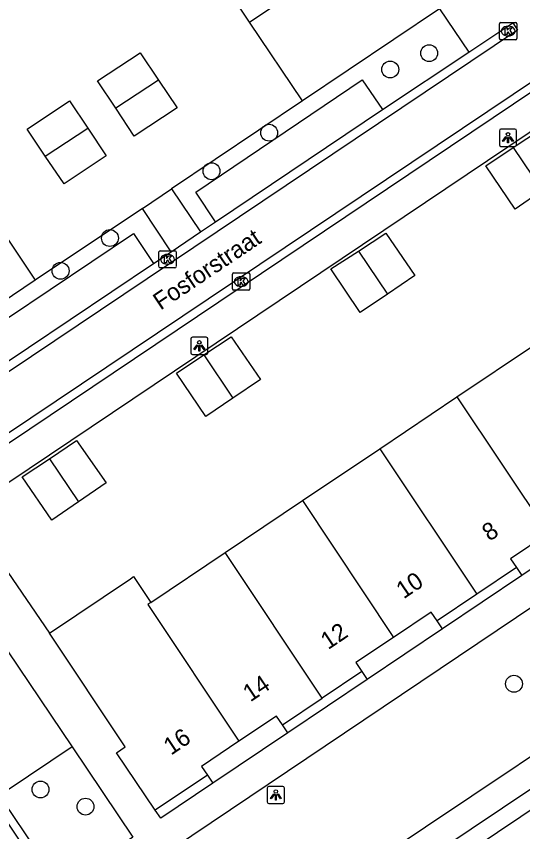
# Model space of a CAD drawing. Extents: x 158797 to 159887, y 384318 to 385255.
# Drawn here: x 159163.97 to 159193.34, y 384481.97 to 384529.23 of the extents above; entities that cross this region are included whole.
import ezdxf

# ---------------------------------------------------------------- set-up
doc = ezdxf.new("R2010")
doc.units = 0
for name, color, linetype in [('IMGEO_Boom', 7, 'Continuous'), ('IMGEO_Groenvoorziening', 7, 'Continuous'), ('IMGEO_Kolk', 7, 'Continuous'), ('IMGEO_Lichtpunt', 7, 'Continuous'), ('IMGEO_Openbare_ruimte_label', 7, 'Continuous'), ('IMGEO_Pand', 7, 'Continuous'), ('IMGEO_Pand_nummerreeks', 7, 'Continuous'), ('IMGEO_Parkeervlak_open', 7, 'Continuous'), ('IMGEO_Rijbaan_lokaal_open', 7, 'Continuous'), ('IMGEO_Voetpad_gesloten', 7, 'Continuous'), ('IMGEO_Voetpad_open', 7, 'Continuous')]:
    doc.layers.add(name, color=color, linetype=linetype)

msp = doc.modelspace()

# ---------------------------------------------------------------- linework, layer by layer
at = {"layer": 'IMGEO_Boom'}
for centre in [(159187.914, 384527.094), (159185.658, 384526.151), (159178.634, 384522.484), (159175.292, 384520.251), (159169.403, 384516.38), (159166.541, 384514.479), (159192.832, 384490.548), (159165.374, 384484.417), (159167.987, 384483.425)]:
    msp.add_circle(centre, 0.489, dxfattribs=at)
at = {"layer": 'IMGEO_Groenvoorziening'}
for points in [[(159180.569, 384524.332), (159172.974, 384519.236)], [(159171.283, 384518.101), (159165.067, 384513.931)], [(159173.77, 384469.796), (159218.275, 384499.657), (159225.084, 384489.227), (159180.738, 384459.571), (159173.77, 384469.796)], [(159192.976, 384497.285), (159193.291, 384496.817)], [(159188.691, 384493.728), (159188.376, 384494.197)], [(159184.009, 384491.264), (159184.323, 384490.796)], [(159179.716, 384487.702), (159179.402, 384488.17)], [(159175.052, 384485.249), (159175.368, 384484.782)]]:
    msp.add_lwpolyline(points, dxfattribs=at)
at = {"layer": 'IMGEO_Kolk'}
for p, q in [((159191.993, 384527.947), (159191.993, 384528.799)), ((159192.068, 384528.873), (159192.92, 384528.873)), ((159192.481, 384528.653), (159192.506, 384528.653)), ((159192.994, 384528.799), (159192.994, 384527.947)), ((159192.504, 384528.093), (159192.479, 384528.093)), ((159192.92, 384527.873), (159192.068, 384527.873)), ((159172.246, 384514.721), (159172.246, 384515.573)), ((159172.321, 384515.647), (159173.173, 384515.647)), ((159172.734, 384515.427), (159172.759, 384515.427)), ((159173.247, 384515.573), (159173.247, 384514.721)), ((159172.757, 384514.867), (159172.732, 384514.867)), ((159173.173, 384514.647), (159172.321, 384514.647)), ((159176.585, 384514.358), (159177.437, 384514.358)), ((159176.51, 384513.432), (159176.51, 384514.284)), ((159176.998, 384514.138), (159177.023, 384514.138)), ((159177.511, 384514.284), (159177.511, 384513.432)), ((159177.021, 384513.578), (159176.996, 384513.578)), ((159177.437, 384513.358), (159176.585, 384513.358))]:
    msp.add_line(p, q, dxfattribs=at)
for points in [[(159191.993, 384527.947), (159191.993, 384528.799)], [(159192.068, 384528.873), (159192.92, 384528.873)], [(159192.314, 384528.573), (159192.437, 384528.573), (159192.437, 384528.422), (159192.567, 384528.573), (159192.731, 384528.573), (159192.585, 384528.422), (159192.738, 384528.173), (159192.586, 384528.173), (159192.501, 384528.337), (159192.437, 384528.27), (159192.437, 384528.173), (159192.314, 384528.173), (159192.314, 384528.573)], [(159192.994, 384528.799), (159192.994, 384527.947)], [(159192.92, 384527.873), (159192.068, 384527.873)], [(159172.246, 384514.721), (159172.246, 384515.573)], [(159172.321, 384515.647), (159173.173, 384515.647)], [(159172.567, 384515.347), (159172.69, 384515.347), (159172.69, 384515.196), (159172.82, 384515.347), (159172.984, 384515.347), (159172.838, 384515.196), (159172.991, 384514.947), (159172.839, 384514.947), (159172.754, 384515.111), (159172.69, 384515.044), (159172.69, 384514.947), (159172.567, 384514.947), (159172.567, 384515.347)], [(159173.247, 384515.573), (159173.247, 384514.721)], [(159173.173, 384514.647), (159172.321, 384514.647)], [(159176.585, 384514.358), (159177.437, 384514.358)], [(159176.51, 384513.432), (159176.51, 384514.284)], [(159176.831, 384514.058), (159176.954, 384514.058), (159176.954, 384513.907), (159177.084, 384514.058), (159177.248, 384514.058), (159177.102, 384513.907), (159177.255, 384513.658), (159177.103, 384513.658), (159177.018, 384513.822), (159176.954, 384513.755), (159176.954, 384513.658), (159176.831, 384513.658), (159176.831, 384514.058)], [(159177.511, 384514.284), (159177.511, 384513.432)], [(159177.437, 384513.358), (159176.585, 384513.358)]]:
    msp.add_lwpolyline(points, dxfattribs=at)
for centre, start, end in [((159192.07, 384528.797), 91.552, 178.448), ((159192.07, 384528.797), 91.552, 178.448), ((159192.918, 384528.797), 1.552, 88.448), ((159192.918, 384528.797), 1.552, 88.448), ((159192.07, 384527.949), 181.552, 268.448), ((159192.07, 384527.949), 181.552, 268.448), ((159192.918, 384527.949), 271.552, 358.448), ((159192.918, 384527.949), 271.552, 358.448), ((159172.323, 384515.571), 91.552, 178.448), ((159172.323, 384515.571), 91.552, 178.448), ((159173.171, 384515.571), 1.552, 88.448), ((159173.171, 384515.571), 1.552, 88.448), ((159172.323, 384514.723), 181.552, 268.448), ((159172.323, 384514.723), 181.552, 268.448), ((159173.171, 384514.723), 271.552, 358.448), ((159173.171, 384514.723), 271.552, 358.448), ((159176.587, 384514.282), 91.552, 178.448), ((159176.587, 384514.282), 91.552, 178.448), ((159177.435, 384514.282), 1.552, 88.448), ((159177.435, 384514.282), 1.552, 88.448), ((159176.587, 384513.434), 181.552, 268.448), ((159176.587, 384513.434), 181.552, 268.448), ((159177.435, 384513.434), 271.552, 358.448), ((159177.435, 384513.434), 271.552, 358.448)]:
    msp.add_arc(centre, 0.0765, start, end, dxfattribs=at)
for centre, major_axis, ratio, start_param, end_param in [((159192.48, 384528.373), (-0.387, 0.002), 0.722429, 4.712389, 7.853982), ((159192.505, 384528.373), (-0.39, 0.002), 0.717154, 1.570796, 4.712389), ((159172.733, 384515.147), (-0.387, 0.002), 0.722429, 4.712389, 7.853982), ((159172.758, 384515.147), (-0.39, 0.002), 0.717154, 1.570796, 4.712389), ((159176.997, 384513.858), (-0.387, 0.002), 0.722429, 4.712389, 7.853982), ((159177.022, 384513.858), (-0.39, 0.002), 0.717154, 1.570796, 4.712389)]:
    msp.add_ellipse(centre, major_axis=major_axis, ratio=ratio, start_param=start_param, end_param=end_param, dxfattribs=at)
at = {"layer": 'IMGEO_Lichtpunt'}
for p, q in [((159191.984, 384522.595), (159191.984, 384521.788)), ((159191.984, 384522.595), (159191.984, 384521.788)), ((159192.886, 384522.69), (159192.078, 384522.69)), ((159192.886, 384522.69), (159192.078, 384522.69)), ((159192.98, 384521.788), (159192.98, 384522.595)), ((159192.98, 384521.788), (159192.98, 384522.595)), ((159192.078, 384521.694), (159192.886, 384521.694)), ((159192.078, 384521.694), (159192.886, 384521.694)), ((159174.992, 384510.63), (159174.184, 384510.63)), ((159174.992, 384510.63), (159174.184, 384510.63)), ((159174.09, 384510.535), (159174.09, 384509.728)), ((159174.09, 384510.535), (159174.09, 384509.728)), ((159175.086, 384509.728), (159175.086, 384510.535)), ((159175.086, 384509.728), (159175.086, 384510.535)), ((159174.184, 384509.634), (159174.992, 384509.634)), ((159174.184, 384509.634), (159174.992, 384509.634)), ((159179.428, 384484.598), (159178.62, 384484.598)), ((159179.428, 384484.598), (159178.62, 384484.598)), ((159178.526, 384484.503), (159178.526, 384483.696)), ((159178.526, 384484.503), (159178.526, 384483.696)), ((159179.522, 384483.696), (159179.522, 384484.503)), ((159179.522, 384483.696), (159179.522, 384484.503)), ((159178.62, 384483.602), (159179.428, 384483.602)), ((159178.62, 384483.602), (159179.428, 384483.602))]:
    msp.add_line(p, q, dxfattribs=at)
for points in [[(159192.358, 384522.259), (159192.397, 384522.231), (159192.209, 384521.969), (159192.171, 384521.996), (159192.358, 384522.259)], [(159192.46, 384522.211), (159192.507, 384522.211), (159192.507, 384521.889), (159192.46, 384521.889), (159192.46, 384522.211)], [(159192.57, 384522.231), (159192.608, 384522.258), (159192.795, 384521.996), (159192.756, 384521.968), (159192.57, 384522.231)], [(159174.464, 384510.199), (159174.503, 384510.171), (159174.315, 384509.909), (159174.277, 384509.936), (159174.464, 384510.199)], [(159174.566, 384510.151), (159174.613, 384510.151), (159174.613, 384509.829), (159174.566, 384509.829), (159174.566, 384510.151)], [(159174.676, 384510.171), (159174.714, 384510.198), (159174.901, 384509.936), (159174.862, 384509.908), (159174.676, 384510.171)], [(159178.9, 384484.167), (159178.939, 384484.139), (159178.751, 384483.877), (159178.713, 384483.904), (159178.9, 384484.167)], [(159179.002, 384484.119), (159179.049, 384484.119), (159179.049, 384483.797), (159179.002, 384483.797), (159179.002, 384484.119)], [(159179.112, 384484.139), (159179.15, 384484.166), (159179.337, 384483.904), (159179.298, 384483.876), (159179.112, 384484.139)]]:
    msp.add_lwpolyline(points, dxfattribs=at)
for centre in [(159192.483, 384522.393), (159174.589, 384510.333), (159179.025, 384484.301)]:
    msp.add_circle(centre, 0.0994, dxfattribs=at)
for centre, start, end in [((159192.078, 384522.595), 90, 180), ((159192.078, 384522.595), 90, 180), ((159192.886, 384522.595), 0, 90), ((159192.886, 384522.595), 0, 90), ((159192.078, 384521.788), 180, 270), ((159192.078, 384521.788), 180, 270), ((159192.886, 384521.788), 270, 0), ((159192.886, 384521.788), 270, 360), ((159174.184, 384510.535), 90, 180), ((159174.184, 384510.535), 90, 180), ((159174.992, 384510.535), 0, 90), ((159174.992, 384510.535), 0, 90), ((159174.184, 384509.728), 180, 270), ((159174.184, 384509.728), 180, 270), ((159174.992, 384509.728), 270, 0), ((159174.992, 384509.728), 270, 360), ((159178.62, 384484.503), 90, 180), ((159178.62, 384484.503), 90, 180), ((159179.428, 384484.503), 0, 90), ((159179.428, 384484.503), 0, 90), ((159178.62, 384483.696), 180, 270), ((159178.62, 384483.696), 180, 270), ((159179.428, 384483.696), 270, 0), ((159179.428, 384483.696), 270, 360)]:
    msp.add_arc(centre, 0.0946, start, end, dxfattribs=at)
at = {"layer": 'IMGEO_Pand'}
for points in [[(159177.505, 384528.901), (159185.434, 384534.241)], [(159177.505, 384528.901), (159174.43, 384533.484)], [(159188.508, 384529.657), (159180.569, 384524.332)], [(159180.569, 384524.332), (159177.505, 384528.901)], [(159169.749, 384523.899), (159168.689, 384525.5), (159171.15, 384527.115), (159172.224, 384525.525)], [(159172.224, 384525.525), (159173.298, 384523.935), (159170.816, 384522.288), (159169.749, 384523.899)], [(159172.224, 384525.525), (159169.749, 384523.899)], [(159165.654, 384521.126), (159164.596, 384522.688), (159167.049, 384524.341), (159168.121, 384522.748)], [(159168.121, 384522.748), (159169.193, 384521.154), (159166.742, 384519.518), (159165.654, 384521.126)], [(159165.654, 384521.126), (159168.121, 384522.748)], [(159192.785, 384521.624), (159194.37, 384522.675), (159196.055, 384520.211), (159194.469, 384519.13)], [(159194.469, 384519.13), (159192.898, 384518.058), (159191.199, 384520.573), (159192.785, 384521.624)], [(159192.785, 384521.624), (159194.469, 384519.13)], [(159161.993, 384518.519), (159165.067, 384513.931)], [(159183.808, 384515.627), (159185.399, 384516.658), (159187.089, 384514.204), (159185.493, 384513.133)], [(159185.493, 384513.133), (159183.915, 384512.073), (159182.217, 384514.596), (159183.808, 384515.627)], [(159183.808, 384515.627), (159185.493, 384513.133)], [(159165.067, 384513.931), (159155.669, 384507.602)], [(159174.847, 384509.603), (159176.437, 384510.65), (159178.133, 384508.182), (159176.538, 384507.1)], [(159189.525, 384507.179), (159194.017, 384510.196)], [(159176.538, 384507.1), (159174.968, 384506.034), (159173.257, 384508.556), (159174.847, 384509.603)], [(159174.847, 384509.603), (159176.538, 384507.1)], [(159185.047, 384504.172), (159189.525, 384507.179)], [(159189.525, 384507.179), (159194.815, 384499.255)], [(159165.89, 384503.591), (159167.469, 384504.637), (159169.187, 384502.193), (159167.577, 384501.093)], [(159180.563, 384501.16), (159185.047, 384504.172)], [(159185.047, 384504.172), (159190.676, 384495.741)], [(159167.577, 384501.093), (159166.026, 384500.033), (159164.311, 384502.544), (159165.89, 384503.591)], [(159165.89, 384503.591), (159167.577, 384501.093)], [(159176.078, 384498.148), (159180.563, 384501.16)], [(159180.563, 384501.16), (159185.853, 384493.237)], [(159194.815, 384499.255), (159192.635, 384497.791), (159192.976, 384497.285)], [(159171.782, 384495.263), (159176.078, 384498.148)], [(159181.706, 384489.717), (159176.078, 384498.148)], [(159192.976, 384497.285), (159190.676, 384495.741)], [(159165.893, 384493.473), (159170.598, 384496.636), (159170.778, 384496.757), (159171.782, 384495.263)], [(159190.676, 384495.741), (159188.376, 384494.197)], [(159171.782, 384495.263), (159171.597, 384495.139), (159176.887, 384487.216)], [(159188.376, 384494.197), (159188.036, 384494.703), (159185.853, 384493.237)], [(159172.03, 384483.22), (159169.79, 384486.546), (159170.291, 384486.885), (159165.893, 384493.473)], [(159185.853, 384493.237), (159183.669, 384491.771), (159184.009, 384491.264)], [(159184.009, 384491.264), (159181.706, 384489.717)], [(159179.402, 384488.17), (159181.706, 384489.717)], [(159179.402, 384488.17), (159179.062, 384488.677), (159176.887, 384487.216)], [(159176.887, 384487.216), (159174.712, 384485.755), (159175.052, 384485.249)], [(159175.052, 384485.249), (159172.03, 384483.22)]]:
    msp.add_lwpolyline(points, dxfattribs=at)
at = {"layer": 'IMGEO_Parkeervlak_open'}
for points in [[(159175.52, 384517.315), (159174.379, 384519.047), (159184.026, 384525.553), (159185.204, 384523.823)], [(159162.243, 384508.41), (159161.078, 384510.145), (159170.771, 384516.645), (159171.938, 384514.9)], [(159167.208, 384486.885), (159163.448, 384484.359)]]:
    msp.add_lwpolyline(points, dxfattribs=at)
at = {"layer": 'IMGEO_Rijbaan_lokaal_open'}
for points in [[(159190.205, 384527.153), (159192.762, 384528.848), (159193.039, 384528.419), (159151.428, 384500.515), (159133.468, 384527.238), (159175.064, 384555.242), (159175.35, 384554.823), (159172.804, 384553.09)], [(159188.508, 384529.657), (159190.205, 384527.153)], [(159166.119, 384478.572), (159153.048, 384498.068), (159198.654, 384528.669)], [(159198.935, 384528.248), (159153.727, 384497.909), (159155.025, 384496.003)], [(159185.204, 384523.823), (159190.205, 384527.153)], [(159175.52, 384517.315), (159185.204, 384523.823)], [(159174.662, 384516.736), (159175.52, 384517.315)], [(159172.956, 384515.586), (159174.662, 384516.736)], [(159171.938, 384514.9), (159172.956, 384515.586)], [(159162.243, 384508.41), (159171.938, 384514.9)], [(159166.298, 384479.197), (159166.262, 384479.244), (159163.274, 384483.682)]]:
    msp.add_lwpolyline(points, dxfattribs=at)
at = {"layer": 'IMGEO_Voetpad_gesloten'}
for points in [[(159214.687, 384500.279), (159171.524, 384471.418)], [(159172.348, 384470.087), (159215.549, 384499.032)]]:
    msp.add_lwpolyline(points, dxfattribs=at)
at = {"layer": 'IMGEO_Voetpad_open'}
for points in [[(159197.375, 384524.94), (159161.04, 384500.556)], [(159171.283, 384518.101), (159172.974, 384519.236)], [(159172.974, 384519.236), (159174.662, 384516.736)], [(159172.956, 384515.586), (159171.283, 384518.101)], [(159164.23, 384475.096), (159210.619, 384506.269)], [(159161.04, 384500.556), (159165.893, 384493.473)], [(159197.649, 384499.743), (159193.291, 384496.817)], [(159159.736, 384497.97), (159167.208, 384486.885)], [(159193.291, 384496.817), (159188.691, 384493.728)], [(159188.691, 384493.728), (159184.323, 384490.796)], [(159184.323, 384490.796), (159179.716, 384487.702)], [(159179.716, 384487.702), (159175.368, 384484.782)], [(159167.208, 384486.885), (159170.738, 384481.648), (159166.971, 384479.12)], [(159175.368, 384484.782), (159172.349, 384482.755), (159172.03, 384483.22)]]:
    msp.add_lwpolyline(points, dxfattribs=at)

# ---------------------------------------------------------------- texts
at = {"layer": 'IMGEO_Openbare_ruimte_label'}
msp.add_text('Fosforstraat', height=1, rotation=33.8649, dxfattribs=at).set_placement((159172.338, 384512.171))
at = {"layer": 'IMGEO_Pand_nummerreeks'}
for s, rotation, p in [('8', 33.8819, (159191.41, 384498.775)), ('10', 33.8819, (159186.433, 384495.434)), ('12', 33.8819, (159182.053, 384492.492)), ('14', 33.8847, (159177.545, 384489.464)), ('16', 33.8847, (159172.945, 384486.375))]:
    msp.add_text(s, height=1, rotation=rotation, dxfattribs=at).set_placement(p)

doc.saveas('drawing.dxf')
